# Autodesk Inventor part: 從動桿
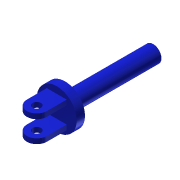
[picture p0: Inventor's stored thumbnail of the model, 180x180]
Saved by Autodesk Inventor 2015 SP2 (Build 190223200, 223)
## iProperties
Created: 2020-03
Part Number: 從動桿
Material: 一般
Document SubType Name: Modeling
Designer: Kuan-Lun Hsu
Density: 1 g/cm^3
Appearance: 藍色 - 牆面油漆 - 亮面
Mass: 8.45252 g
Surface Area: 43.268 cm^2
Volume: 8.45252 cm^3
Author: Kuan-Lun Hsu
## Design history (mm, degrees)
sketch "草圖1"
  geometry: L1 (0, 0)-(5, 0); L2 (5, 0)-(5, 58); L3 (5, 58)-(0, 58); L4 (0, 58)-(0, 0); L5 (0, 0)-(12, 0); L6 (12, 0)-(12, 5); L7 (12, 5)-(0, 5); L8 (0, 5)-(0, 0)
  constraints: 16 end point, 4 parallel, 2 horizontal, 2 perpendicular
  dimensions: "d0" = 10 diameter of L2 L4; "d1" = 58 distance of L1.end L2.end; "d2" = 5 distance of L5.end L6.end; "d3" = 12 distance of L6.end L7.end
revolve "迴轉1" sketch "草圖1" stored, may be unused: angle "d4" = 90 deg
node "工作平面1"
sketch "草圖2"
  geometry: L1 (-6, 0)-(6, 0); L2 (6, 0)-(6, -12); L3 (6, -12)-(-6, -12); L4 (-6, -12)-(-6, 0); L5 (-12, 0)-(12, 0) reference; 2 further points
  constraints: 8 end point, 2 midpoint, 2 parallel, 1 horizontal, 1 horizontal alignment, 1 perpendicular, 2 other
  dimensions: "d6" = 12 distance of L1.end L2.end; "d7" = 12 distance of L2.end L3.end
extrude "擠出1" join sketch "草圖2" distance "d8" = 3; taper "d9" = 0 deg
sketch "草圖3"
  geometry: C1 r 2.5 at (0, -12); A1 r 6 centre (0, -12) between (-6, -12) and (6, -12) reference; 1 further point
  constraints: 1 centre point, 1 coincident
  dimensions: "d10" = 5 diameter of C1
extrude "擠出2" cut sketch "草圖3" stored distance "d11" = 3; taper "d12" = 0 deg
mirror "鏡射1"
node "實體1"
other parameters: "d5" = 5
